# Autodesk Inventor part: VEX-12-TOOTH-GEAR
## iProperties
Created: 2007-08
Part Number: VEX-12-TOOTH-GEAR
Material: ABS Plastic
Document SubType Name: Modeling
Density: 1.06 g/cm^3
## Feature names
1. Base1
